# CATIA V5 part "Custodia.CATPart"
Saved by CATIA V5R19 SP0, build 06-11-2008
Part number: Custodia
Bounding box of the stored display mesh (mm): x -11.5 to 42, y -11.5 to 11.5, z -3 to 70
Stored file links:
  C:\Users\sisca\Desktop\HELTEC_CASE\Custodia.CATPart
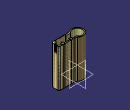
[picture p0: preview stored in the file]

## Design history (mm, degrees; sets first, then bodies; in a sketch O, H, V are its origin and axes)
Set1
  DatumCurve1 to DatumCurve13
  DatumSurface1
  DatumSurface2
  CLDGeom1 "Tessellation.1"
Body1 (main body)
  Sketch1 on xy-plane, origin (0, 0, 0), H (1, 0, 0), V (0, 1, 0)
    arc A1 centre (0, 0) radius 9.5 from (8.0777, 5) to (8.0777, -5) ccw
    line L1 (8.0777, 5) -> (40, 5)
    line L2 (40, 5) -> (40, -5)
    line L3 (40, -5) -> (8.0777, -5)
    line L4 (42, -8) -> (42, 7)
    line L5 (9.1241, 7) -> (42, 7)
    arc A2 centre (0, 0) radius 11.5 from (9.1241, 7) to (8.2614, -8) ccw
    line L6 (42, -8) -> (8.2614, -8)
    radius A1 = 9.5
    length L2 = 10
    distance L1 H = 5
    distance L2 V = 40
    distance L5 H = 7
    distance L3 L6 = 3
    radius A2 = 11.5
    horizontal: L1 H, L3 H
    vertical: L2 V
    concentricity: A2 A1
  Pad1: profile Sketch1, direction (0, 0, 1), length 70, opposite side length 2
  Chamfer1: length 2, angle 45, on edge [face of Pad1 from Sketch1.L2 | face of Pad1 from Sketch1.L3]; edge [face of Pad1 from Sketch1.L1 | face of Pad1 from Sketch1.L2]; edge [face of Pad1 from Sketch1.L4 | face of Pad1 from Sketch1.L6]; edge [face of Pad1 from Sketch1.L5 | face of Pad1 from Sketch1.L4]
  Fillet1: radius 5, on edge [face of Pad1 from Sketch1.A2 | face of Pad1 from Sketch1.L5]; edge [face of Pad1 from Sketch1.L6 | face of Pad1 from Sketch1.A2]
  Sketch2 on start face of Pad1, origin (0, 0, -2), H (1, 0, 0), V (0, -1, 0)
    line L1 (15.2724, 7.5) -> (35.2724, 7.5)
    line L2 (35.2724, 7.5) -> (35.2724, 4.5)
    line L3 (35.2724, 4.5) -> (15.2724, 4.5)
    line L4 (15.2724, 4.5) -> (15.2724, 7.5)
    reference projected line E1 (9.1241, 8) -> (42, 8) from edge [start face of Pad1 | face of Pad1 from Sketch1.L6]
    reference projected line E2 (33.7724, 0) -> (33.7724, 5) from edge of DatumCurve1
    length L1 = 20
    distance L1 E1 = 0.5
    distance L2 E2 = 1.5
    length L2 = 3
    horizontal: L1 H, L3 H
    vertical: L2 V, L4 V
  Pocket1: profile Sketch2, direction (0, 0, 1), length 72, opposite side length -13
  Sketch3 on start face of Pad1, origin (0, 0, -2), H (1, 0, 0), V (0, -1, 0)
    line L1 (16.7724, 7.5) -> (20.7724, 7.5)
    line L2 (20.7724, 7.5) -> (20.7724, 3.7205)
    line L3 (20.7724, 3.7205) -> (16.7724, 3.7205)
    line L4 (16.7724, 3.7205) -> (16.7724, 7.5)
    reference projected line E1 (9.1241, 8) -> (42, 8) from edge [start face of Pad1 | face of Pad1 from Sketch1.L6]
    reference projected line E2 (16.7724, 1.2) -> (16.7724, 6.2) from edge of DatumCurve2
    distance L1 E1 = 0.5
    distance L4 L2 = 4
    distance L4 E2 = 0
    horizontal: L1 H, L3 H
    vertical: L2 V, L4 V
  Pocket2: profile Sketch3, direction (0, 0, 1), length 20
  Sketch4 on start face of Pad1, origin (0, 0, -2), H (1, 0, 0), V (0, -1, 0)
    line L1 (36.5953, 1.7) -> (36.5953, 3.2)
    line L2 (36.5953, 3.2) -> (40, 3.2)
    line L3 (40, 3.2) -> (40, -2.3)
    line L4 (40, -2.3) -> (36.5953, -2.3)
    point P5 (36.5953, -2.3)
    line L5 (36.5953, -2.3) -> (36.5953, -0.8)
    line L6 (36.5953, -0.8) -> (38.5564, -0.8)
    line L7 (38.5564, -0.8) -> (38.5564, 1.7)
    line L8 (38.5564, 1.7) -> (36.5953, 1.7)
    reference projected line E1 (40, 5) -> (40, -5) from edge [face of Pad1 from Sketch1.L2 | start face of Pad1]
    reference projected line E2 (38.0564, 1.2) -> (38.0564, -0.3) from edge of DatumCurve3
    reference projected line E3 (38.0564, 1.2) -> (36.6422, 1.2) from edge of DatumCurve4
    line L9 (14.0176, 1.7) -> (14.0176, 5)
    line L10 (14.0176, 5) -> (10.6128, 5)
    line L11 (10.6128, 5) -> (10.6128, -2.3)
    line L12 (10.6128, -2.3) -> (14.0176, -2.3)
    line L13 (14.0176, -2.3) -> (14.0176, -0.8)
    line L14 (14.0176, -0.8) -> (12.0564, -0.8)
    line L15 (12.0564, -0.8) -> (12.0564, 1.7)
    line L16 (12.0564, 1.7) -> (14.0176, 1.7)
    reference projected line E4 (13.9706, 1.2) -> (12.5564, 1.2) from edge of DatumCurve6
    reference projected line E5 (13.9706, -0.3) -> (12.5564, -0.3) from edge of DatumCurve7
    reference projected line E6 (12.5564, 1.2) -> (12.5564, -0.3) from edge of DatumCurve8
    reference projected line E7 (8.0777, 5) -> (40, 5) from edge [face of Pad1 from Sketch1.L3 | start face of Pad1]
    distance L2 L4 = 5.5
    distance L3 E1 = 0
    length L1 = 1.5
    length L5 = 1.5
    distance L7 E2 = 0.5
    distance L8 E3 = 0.5
    distance L16 E4 = 0.5
    distance L14 E5 = 0.5
    distance E6 L15 = 0.5
    distance L10 E7 = 0
    length L13 = 1.5
    vertical: L1 V, L3 V, L5 V, L7 V
    horizontal: L2 H, L4 H, L6 H, L8 H
    coincidence: P5 L1
  Pad2: profile Sketch4, direction (0, 0, 1), length 49
  Chamfer2: length 0.5, angle 45, on edge [face of Pad2 from Sketch4.L13 | face of Pad2 from Sketch4.L14]; edge [face of Pad2 from Sketch4.L16 | face of Pad2 from Sketch4.L9]; edge [face of Pad2 from Sketch4.L6 | face of Pad2 from Sketch4.L5]; edge [face of Pad2 from Sketch4.L1 | face of Pad2 from Sketch4.L8]
  Chamfer3: length 0.5, angle 45, on edge [face of Pad2 from Sketch4.L9 | face of Pad1 from Sketch1.L3]; edge [face of Pad1 from Sketch1.L3 | face of Pad2 from Sketch4.L11]; edge [face of Pad2 from Sketch4.L4 | face of Pad1 from Sketch1.L2]; edge [face of Chamfer1 | face of Pad2 from Sketch4.L2]
  Sketch5 on face of Pad1 from Sketch1.L6, origin (0, -8, 0), H (1, 0, 0), V (0, 0, 1)
    line L1 (17, 42) -> (32, 42)
    line L2 (32, 42) -> (32, 16)
    line L3 (32, 16) -> (17, 16)
    line L4 (17, 16) -> (17, 42)
    reference projected line E1 (9.1241, -2) -> (42, -2) from edge [face of Pad2 | face of Pad1 from Sketch1.L6]
    reference projected line E2 (42, -2) -> (42, 70) from edge [face of Pad1 from Sketch1.L4 | face of Chamfer1]
    length L2 = 26
    length L3 = 15
    distance L3 E1 = 18
    distance L2 E2 = 10
    horizontal: L1 H, L3 H
    vertical: L2 V, L4 V
  Pocket3: profile Sketch5, direction (0, 1, 0), length 2
  Sketch6 on face of Pad2, origin (0, 0, -2), H (1, 0, 0), V (0, -1, 0)
    arc A1 centre (0, 0) radius 11.5 from (7.893, 8.3636) to (7.893, -8.3636) ccw
    point P1 (7.893, 8.3636)
    point P2 (7.893, -8.3636)
    point P3 (7.893, 8.3636)
    point P4 (11.3248, 7)
    point P5 (11.3248, 7)
    point P6 (40, 7)
    point P7 (40, 7)
    point P8 (42, 5)
    point P9 (42, 5)
    point P10 (42, -5)
    point P11 (42, -5)
    point P12 (40, -7)
    point P13 (40, -7)
    point P14 (11.3248, -7)
    point P15 (11.3248, -7)
    point P16 (7.893, -8.3636)
    arc A2 centre (11.3248, 12) radius 5 from (7.893, 8.3636) to (11.3248, 7) ccw
    line L1 (11.3248, 7) -> (40, 7)
    line L2 (40, 7) -> (42, 5)
    line L3 (42, 5) -> (42, -5)
    line L4 (42, -5) -> (40, -7)
    line L5 (40, -7) -> (11.3248, -7)
    arc A3 centre (11.3248, -12) radius 5 from (11.3248, -7) to (7.893, -8.3636) ccw
    coincidence: P1 P3, P2 P16, P4 P5, P6 P7, P8 P9, P10 P11, P12 P13, P14 P15
  Pad3: profile Sketch6, direction (0, 0, -1), length 1
  Sketch7 on end face of Pad3, origin (0, 0, -3), H (1, 0, 0), V (0, -1, 0)
    construction line L1 (21.9, 2.7) -> (28.9, 2.7)
    point P2 (28.9, 2.7)
    line L2 (21.9, 4.7) -> (28.9, 4.7)
    line L3 (28.9, 0.7) -> (21.9, 0.7)
    arc A1 centre (28.9, 2.7) radius 2 from (28.9, 4.7) to (28.9, 0.7) cw
    arc A2 centre (21.9, 2.7) radius 2 from (21.9, 0.7) to (21.9, 4.7) cw
    reference projected line E1 (40, 7) -> (11.3248, 7) from edge [face of Pad3 | end face of Pad3]
    reference projected line E2 (42, -5) -> (42, 5) from edge [face of Pad3 | end face of Pad3]
    distance L1 L2 = 2
    length L1 = 7
    distance L2 E1 = 2.3
    distance P2 E2 = 13.1
    horizontal: L1 H
    tangency: A1 L2, A2 L2, A1 L3, A2 L3
  Pocket4: profile Sketch7, direction (0, 0, 1), length 1
  Sketch8 on start face of Pad3, origin (0, 0, -2), H (1, 0, 0), V (0, 1, 0)
    circle A1 centre (32.5, 4.5) radius 3
    reference projected circle E1 centre (32.5, 4.5) radius 1.65 from edge of DatumCurve9
    circle A2 centre (17, 4.5) radius 3
    reference projected circle E2 centre (17, 4.5) radius 1.65 from edge of DatumCurve10
    radius A1 = 3
    radius A2 = 3
    concentricity: A1 E1, A2 E2
  Pad4: profile Sketch8, direction (0, 0, 1), length 72, opposite side length 1
  Sketch9 on face of Pad4, origin (0, 0, 70), H (1, 0, 0), V (0, 1, 0)
    circle A1 centre (32.5, 4.5) radius 2.5
    reference projected circle E1 centre (32.5, 4.5) radius 1.65 from edge of DatumCurve11
    circle A2 centre (17, 4.5) radius 2.5
    reference projected circle E2 centre (17, 4.5) radius 1.65 from edge of DatumCurve12
    radius A1 = 2.5
    radius A2 = 2.5
    concentricity: A1 E1, A2 E2
  Pocket5: profile Sketch9, direction (0, 0, -1), length 7
  Sketch10 on face of Pad4, origin (0, 0, 70), H (1, 0, 0), V (0, 1, 0)
    line L1 (46.0413, 2) -> (39.3818, 2)
    line L2 (39.3818, 2) -> (39.3818, -2)
    line L3 (39.3818, -2) -> (46.0413, -2)
    line L4 (46.0413, -2) -> (46.0413, 2)
    reference projected line E1 (40, 7) -> (11.3248, 7) from edge of DatumCurve13
    length L2 = 4
    distance L1 E1 = 5
    horizontal: L1 H, L3 H
    vertical: L2 V, L4 V
  Pocket6: profile Sketch10, direction (0, 0, -1), length 13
